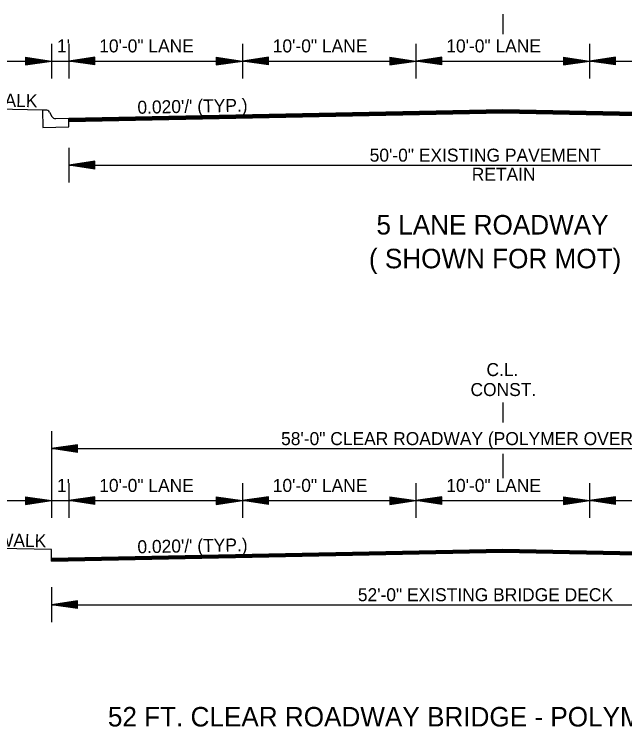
# Model space of a CAD drawing. Extents: x 550980 to 1930787, y -1972975 to 596640.
# Drawn here: x 551281.8 to 551633.5, y -1966644.6 to -1966233.8 of the extents above; entities that cross this region are included whole.
import ezdxf

# ---------------------------------------------------------------- set-up
doc = ezdxf.new("R2010")
doc.units = 0
doc.layers.add('R_Border', color=7, linetype='Continuous')
doc.layers.add('R_Draft', color=7, linetype='Continuous')

msp = doc.modelspace()

# ---------------------------------------------------------------- linework, layer by layer
at = {"layer": 'R_Border'}
for p, q in [((551563.18, -1966233.82), (551563.18, -1966245.39)), ((551303.18, -1966250.82), (551303.18, -1966270.82)), ((551313.18, -1966250.82), (551313.18, -1966270.82)), ((551413.18, -1966250.82), (551413.18, -1966270.82)), ((551513.18, -1966250.82), (551513.18, -1966270.82)), ((551613.18, -1966250.82), (551613.18, -1966270.82)), ((551288.18, -1966258.57), (551303.18, -1966260.82)), ((551288.18, -1966258.57), (551288.18, -1966263.07)), ((551288.18, -1966258.95), (551300.67, -1966260.82)), ((551288.18, -1966259.33), (551298.09, -1966260.82)), ((551288.18, -1966259.71), (551295.6, -1966260.82)), ((551288.18, -1966260.1), (551293.05, -1966260.82)), ((551328.18, -1966258.57), (551313.18, -1966260.82)), ((551328.18, -1966258.95), (551315.68, -1966260.82)), ((551328.18, -1966259.33), (551318.26, -1966260.82)), ((551328.18, -1966259.71), (551320.76, -1966260.82)), ((551328.18, -1966260.09), (551323.3, -1966260.82)), ((551328.18, -1966263.07), (551328.18, -1966258.57)), ((551398.18, -1966258.57), (551413.18, -1966260.82)), ((551398.18, -1966258.57), (551398.18, -1966263.07)), ((551398.18, -1966258.95), (551410.67, -1966260.82)), ((551398.18, -1966259.33), (551408.09, -1966260.82)), ((551398.18, -1966259.71), (551405.6, -1966260.82)), ((551398.18, -1966260.1), (551403.05, -1966260.82)), ((551428.18, -1966258.57), (551413.18, -1966260.82)), ((551428.18, -1966258.95), (551415.68, -1966260.82)), ((551428.18, -1966259.33), (551418.26, -1966260.82)), ((551428.18, -1966259.71), (551420.76, -1966260.82)), ((551428.18, -1966260.09), (551423.3, -1966260.82)), ((551428.18, -1966263.07), (551428.18, -1966258.57)), ((551498.18, -1966258.57), (551513.18, -1966260.82)), ((551498.18, -1966258.57), (551498.18, -1966263.07)), ((551498.18, -1966258.95), (551510.67, -1966260.82)), ((551498.18, -1966259.33), (551508.09, -1966260.82)), ((551498.18, -1966259.71), (551505.6, -1966260.82)), ((551498.18, -1966260.1), (551503.05, -1966260.82)), ((551528.18, -1966258.57), (551513.18, -1966260.82)), ((551528.18, -1966258.95), (551515.68, -1966260.82)), ((551528.18, -1966259.33), (551518.26, -1966260.82)), ((551528.18, -1966259.71), (551520.76, -1966260.82)), ((551528.18, -1966260.09), (551523.3, -1966260.82)), ((551528.18, -1966263.07), (551528.18, -1966258.57)), ((551598.18, -1966258.57), (551613.18, -1966260.82)), ((551598.18, -1966258.57), (551598.18, -1966263.07)), ((551598.18, -1966258.95), (551610.67, -1966260.82)), ((551598.18, -1966259.33), (551608.09, -1966260.82)), ((551598.18, -1966259.71), (551605.6, -1966260.82)), ((551598.18, -1966260.1), (551603.05, -1966260.82)), ((551628.18, -1966258.57), (551613.18, -1966260.82)), ((551628.18, -1966258.95), (551615.68, -1966260.82)), ((551628.18, -1966259.33), (551618.26, -1966260.82)), ((551628.18, -1966259.71), (551620.76, -1966260.82)), ((551628.18, -1966260.09), (551623.3, -1966260.82)), ((551628.18, -1966263.07), (551628.18, -1966258.57)), ((551273.18, -1966260.82), (551853.18, -1966260.82)), ((551288.18, -1966260.47), (551290.55, -1966260.82)), ((551288.18, -1966263.07), (551303.18, -1966260.82)), ((551288.18, -1966261.56), (551293.05, -1966260.82)), ((551288.18, -1966262.32), (551298.09, -1966260.82)), ((551288.18, -1966262.7), (551300.67, -1966260.82)), ((551288.18, -1966261.94), (551295.6, -1966260.82)), ((551288.18, -1966261.18), (551290.55, -1966260.82)), ((551328.18, -1966263.07), (551313.18, -1966260.82)), ((551328.18, -1966262.7), (551315.68, -1966260.82)), ((551328.18, -1966262.32), (551318.26, -1966260.82)), ((551328.18, -1966261.94), (551320.76, -1966260.82)), ((551328.18, -1966261.55), (551323.3, -1966260.82)), ((551328.18, -1966260.47), (551325.81, -1966260.82)), ((551328.18, -1966261.18), (551325.81, -1966260.82)), ((551398.18, -1966260.47), (551400.55, -1966260.82)), ((551398.18, -1966263.07), (551413.18, -1966260.82)), ((551398.18, -1966261.56), (551403.05, -1966260.82)), ((551398.18, -1966262.32), (551408.09, -1966260.82)), ((551398.18, -1966262.7), (551410.67, -1966260.82)), ((551398.18, -1966261.94), (551405.6, -1966260.82)), ((551398.18, -1966261.18), (551400.55, -1966260.82)), ((551428.18, -1966263.07), (551413.18, -1966260.82)), ((551428.18, -1966262.7), (551415.68, -1966260.82)), ((551428.18, -1966262.32), (551418.26, -1966260.82)), ((551428.18, -1966261.94), (551420.76, -1966260.82)), ((551428.18, -1966261.55), (551423.3, -1966260.82)), ((551428.18, -1966260.47), (551425.81, -1966260.82)), ((551428.18, -1966261.18), (551425.81, -1966260.82)), ((551498.18, -1966260.47), (551500.55, -1966260.82)), ((551498.18, -1966263.07), (551513.18, -1966260.82)), ((551498.18, -1966261.56), (551503.05, -1966260.82)), ((551498.18, -1966262.32), (551508.09, -1966260.82)), ((551498.18, -1966262.7), (551510.67, -1966260.82)), ((551498.18, -1966261.94), (551505.6, -1966260.82)), ((551498.18, -1966261.18), (551500.55, -1966260.82)), ((551528.18, -1966263.07), (551513.18, -1966260.82)), ((551528.18, -1966262.7), (551515.68, -1966260.82)), ((551528.18, -1966262.32), (551518.26, -1966260.82)), ((551528.18, -1966261.94), (551520.76, -1966260.82)), ((551528.18, -1966261.55), (551523.3, -1966260.82)), ((551528.18, -1966260.47), (551525.81, -1966260.82)), ((551528.18, -1966261.18), (551525.81, -1966260.82)), ((551598.18, -1966260.47), (551600.55, -1966260.82)), ((551598.18, -1966263.07), (551613.18, -1966260.82)), ((551598.18, -1966261.56), (551603.05, -1966260.82)), ((551598.18, -1966262.32), (551608.09, -1966260.82)), ((551598.18, -1966262.7), (551610.67, -1966260.82)), ((551598.18, -1966261.94), (551605.6, -1966260.82)), ((551598.18, -1966261.18), (551600.55, -1966260.82)), ((551628.18, -1966263.07), (551613.18, -1966260.82)), ((551628.18, -1966262.7), (551615.68, -1966260.82)), ((551628.18, -1966262.32), (551618.26, -1966260.82)), ((551628.18, -1966261.94), (551620.76, -1966260.82)), ((551628.18, -1966261.55), (551623.3, -1966260.82)), ((551628.18, -1966260.47), (551625.81, -1966260.82)), ((551628.18, -1966261.18), (551625.81, -1966260.82)), ((551298.08, -1966289.13), (551238.08, -1966287.93)), ((551313.18, -1966310.82), (551313.18, -1966330.82)), ((551328.18, -1966318.57), (551313.18, -1966320.82)), ((551313.18, -1966320.82), (551813.18, -1966320.82)), ((551328.18, -1966323.07), (551313.18, -1966320.82)), ((551328.18, -1966318.95), (551315.68, -1966320.82)), ((551328.18, -1966322.7), (551315.68, -1966320.82)), ((551328.18, -1966319.33), (551318.26, -1966320.82)), ((551328.18, -1966322.32), (551318.26, -1966320.82)), ((551328.18, -1966319.71), (551320.76, -1966320.82)), ((551328.18, -1966321.94), (551320.76, -1966320.82)), ((551328.18, -1966320.09), (551323.3, -1966320.82)), ((551328.18, -1966321.55), (551323.3, -1966320.82)), ((551328.18, -1966320.47), (551325.81, -1966320.82)), ((551328.18, -1966321.18), (551325.81, -1966320.82)), ((551328.18, -1966323.07), (551328.18, -1966318.57)), ((551563.18, -1966457.67), (551563.18, -1966469.24)), ((551303.18, -1966474.25), (551303.18, -1966524.25)), ((551318.18, -1966482), (551303.18, -1966484.25)), ((551318.18, -1966486.5), (551318.18, -1966482)), ((551303.18, -1966484.25), (551823.18, -1966484.25)), ((551318.18, -1966486.5), (551303.18, -1966484.25)), ((551318.18, -1966482.37), (551305.68, -1966484.25)), ((551318.18, -1966486.12), (551305.68, -1966484.25)), ((551318.18, -1966482.76), (551308.26, -1966484.25)), ((551318.18, -1966485.74), (551308.26, -1966484.25)), ((551318.18, -1966483.13), (551310.76, -1966484.25)), ((551318.18, -1966485.37), (551310.76, -1966484.25)), ((551318.18, -1966483.51), (551313.3, -1966484.25)), ((551318.18, -1966484.98), (551313.3, -1966484.25)), ((551318.18, -1966483.9), (551315.81, -1966484.25)), ((551318.18, -1966484.6), (551315.81, -1966484.25)), ((551563.18, -1966487.25), (551563.18, -1966501.25)), ((551303.18, -1966504.25), (551303.18, -1966524.25)), ((551313.18, -1966504.25), (551313.18, -1966524.25)), ((551413.18, -1966504.25), (551413.18, -1966524.25)), ((551513.18, -1966504.25), (551513.18, -1966524.25)), ((551613.18, -1966504.25), (551613.18, -1966524.25)), ((551273.18, -1966514.25), (551853.18, -1966514.25)), ((551288.18, -1966512), (551303.18, -1966514.25)), ((551288.18, -1966512), (551288.18, -1966516.5)), ((551288.18, -1966512.37), (551300.67, -1966514.25)), ((551288.18, -1966512.76), (551298.09, -1966514.25)), ((551288.18, -1966513.13), (551295.6, -1966514.25)), ((551288.18, -1966513.52), (551293.05, -1966514.25)), ((551288.18, -1966513.9), (551290.55, -1966514.25)), ((551288.18, -1966516.5), (551303.18, -1966514.25)), ((551288.18, -1966514.98), (551293.05, -1966514.25)), ((551288.18, -1966515.74), (551298.09, -1966514.25)), ((551288.18, -1966516.12), (551300.67, -1966514.25)), ((551288.18, -1966515.37), (551295.6, -1966514.25)), ((551288.18, -1966514.6), (551290.55, -1966514.25)), ((551328.18, -1966512), (551313.18, -1966514.25)), ((551328.18, -1966516.5), (551313.18, -1966514.25)), ((551328.18, -1966512.37), (551315.68, -1966514.25)), ((551328.18, -1966516.12), (551315.68, -1966514.25)), ((551328.18, -1966512.76), (551318.26, -1966514.25)), ((551328.18, -1966515.74), (551318.26, -1966514.25)), ((551328.18, -1966513.13), (551320.76, -1966514.25)), ((551328.18, -1966515.37), (551320.76, -1966514.25)), ((551328.18, -1966513.51), (551323.3, -1966514.25)), ((551328.18, -1966514.98), (551323.3, -1966514.25)), ((551328.18, -1966513.9), (551325.81, -1966514.25)), ((551328.18, -1966514.6), (551325.81, -1966514.25)), ((551328.18, -1966516.5), (551328.18, -1966512)), ((551398.18, -1966512), (551413.18, -1966514.25)), ((551398.18, -1966512), (551398.18, -1966516.5)), ((551398.18, -1966512.37), (551410.67, -1966514.25)), ((551398.18, -1966512.76), (551408.09, -1966514.25)), ((551398.18, -1966513.13), (551405.6, -1966514.25)), ((551398.18, -1966513.52), (551403.05, -1966514.25)), ((551398.18, -1966513.9), (551400.55, -1966514.25)), ((551398.18, -1966516.5), (551413.18, -1966514.25)), ((551398.18, -1966514.98), (551403.05, -1966514.25)), ((551398.18, -1966515.74), (551408.09, -1966514.25)), ((551398.18, -1966516.12), (551410.67, -1966514.25)), ((551398.18, -1966515.37), (551405.6, -1966514.25)), ((551398.18, -1966514.6), (551400.55, -1966514.25)), ((551428.18, -1966512), (551413.18, -1966514.25)), ((551428.18, -1966516.5), (551413.18, -1966514.25)), ((551428.18, -1966512.37), (551415.68, -1966514.25)), ((551428.18, -1966516.12), (551415.68, -1966514.25)), ((551428.18, -1966512.76), (551418.26, -1966514.25)), ((551428.18, -1966515.74), (551418.26, -1966514.25)), ((551428.18, -1966513.13), (551420.76, -1966514.25)), ((551428.18, -1966515.37), (551420.76, -1966514.25)), ((551428.18, -1966513.51), (551423.3, -1966514.25)), ((551428.18, -1966514.98), (551423.3, -1966514.25)), ((551428.18, -1966513.9), (551425.81, -1966514.25)), ((551428.18, -1966514.6), (551425.81, -1966514.25)), ((551428.18, -1966516.5), (551428.18, -1966512)), ((551498.18, -1966512), (551513.18, -1966514.25)), ((551498.18, -1966512), (551498.18, -1966516.5)), ((551498.18, -1966512.37), (551510.67, -1966514.25)), ((551498.18, -1966512.76), (551508.09, -1966514.25)), ((551498.18, -1966513.13), (551505.6, -1966514.25)), ((551498.18, -1966513.52), (551503.05, -1966514.25)), ((551498.18, -1966513.9), (551500.55, -1966514.25)), ((551498.18, -1966516.5), (551513.18, -1966514.25)), ((551498.18, -1966514.98), (551503.05, -1966514.25)), ((551498.18, -1966515.74), (551508.09, -1966514.25)), ((551498.18, -1966516.12), (551510.67, -1966514.25)), ((551498.18, -1966515.37), (551505.6, -1966514.25)), ((551498.18, -1966514.6), (551500.55, -1966514.25)), ((551528.18, -1966512), (551513.18, -1966514.25)), ((551528.18, -1966516.5), (551513.18, -1966514.25)), ((551528.18, -1966512.37), (551515.68, -1966514.25)), ((551528.18, -1966516.12), (551515.68, -1966514.25)), ((551528.18, -1966512.76), (551518.26, -1966514.25)), ((551528.18, -1966515.74), (551518.26, -1966514.25)), ((551528.18, -1966513.13), (551520.76, -1966514.25)), ((551528.18, -1966515.37), (551520.76, -1966514.25)), ((551528.18, -1966513.51), (551523.3, -1966514.25)), ((551528.18, -1966514.98), (551523.3, -1966514.25)), ((551528.18, -1966513.9), (551525.81, -1966514.25)), ((551528.18, -1966514.6), (551525.81, -1966514.25)), ((551528.18, -1966516.5), (551528.18, -1966512)), ((551598.18, -1966512), (551613.18, -1966514.25)), ((551598.18, -1966512), (551598.18, -1966516.5)), ((551598.18, -1966512.37), (551610.67, -1966514.25)), ((551598.18, -1966512.76), (551608.09, -1966514.25)), ((551598.18, -1966513.13), (551605.6, -1966514.25)), ((551598.18, -1966513.52), (551603.05, -1966514.25)), ((551598.18, -1966513.9), (551600.55, -1966514.25)), ((551598.18, -1966516.5), (551613.18, -1966514.25)), ((551598.18, -1966514.98), (551603.05, -1966514.25)), ((551598.18, -1966515.74), (551608.09, -1966514.25)), ((551598.18, -1966516.12), (551610.67, -1966514.25)), ((551598.18, -1966515.37), (551605.6, -1966514.25)), ((551598.18, -1966514.6), (551600.55, -1966514.25)), ((551628.18, -1966512), (551613.18, -1966514.25)), ((551628.18, -1966516.5), (551613.18, -1966514.25)), ((551628.18, -1966512.37), (551615.68, -1966514.25)), ((551628.18, -1966516.12), (551615.68, -1966514.25)), ((551628.18, -1966512.76), (551618.26, -1966514.25)), ((551628.18, -1966515.74), (551618.26, -1966514.25)), ((551628.18, -1966513.13), (551620.76, -1966514.25)), ((551628.18, -1966515.37), (551620.76, -1966514.25)), ((551628.18, -1966513.51), (551623.3, -1966514.25)), ((551628.18, -1966514.98), (551623.3, -1966514.25)), ((551628.18, -1966513.9), (551625.81, -1966514.25)), ((551628.18, -1966514.6), (551625.81, -1966514.25)), ((551628.18, -1966516.5), (551628.18, -1966512)), ((551303.18, -1966564.25), (551303.18, -1966584.25)), ((551318.18, -1966572), (551303.18, -1966574.25)), ((551318.18, -1966572.37), (551305.68, -1966574.25)), ((551318.18, -1966576.5), (551318.18, -1966572)), ((551303.18, -1966574.25), (551823.18, -1966574.25)), ((551318.18, -1966576.5), (551303.18, -1966574.25)), ((551318.18, -1966576.12), (551305.68, -1966574.25)), ((551318.18, -1966572.76), (551308.26, -1966574.25)), ((551318.18, -1966575.74), (551308.26, -1966574.25)), ((551318.18, -1966573.13), (551310.76, -1966574.25)), ((551318.18, -1966575.37), (551310.76, -1966574.25)), ((551318.18, -1966573.51), (551313.3, -1966574.25)), ((551318.18, -1966574.98), (551313.3, -1966574.25)), ((551318.18, -1966573.9), (551315.81, -1966574.25)), ((551318.18, -1966574.6), (551315.81, -1966574.25))]:
    msp.add_line(p, q, dxfattribs=at)
for points in [[(551313.18, -1966293.82), (551563.18, -1966288.82), (551813.18, -1966293.82)], [(551313.18, -1966294.12), (551563.18, -1966289.12), (551813.18, -1966294.12)], [(551313.18, -1966294.42), (551563.18, -1966289.42), (551813.18, -1966294.42)], [(551313.18, -1966294.72), (551563.18, -1966289.72), (551813.18, -1966294.72)], [(551313.18, -1966295.02), (551563.18, -1966290.02), (551813.18, -1966295.02)], [(551313.18, -1966295.32), (551563.18, -1966290.32), (551813.18, -1966295.32)], [(551313.18, -1966295.62), (551563.18, -1966290.62), (551813.18, -1966295.62)], [(551303.18, -1966549.25), (551303.18, -1966542.45), (551243.18, -1966541.25), (551243.18, -1966541.25)], [(551303.18, -1966547.45), (551563.18, -1966542.25), (551823.18, -1966547.45)], [(551303.18, -1966547.75), (551563.18, -1966542.55), (551823.18, -1966547.75)], [(551303.18, -1966548.05), (551563.18, -1966542.85), (551823.18, -1966548.05)], [(551303.18, -1966548.35), (551563.18, -1966543.15), (551823.18, -1966548.35)], [(551303.18, -1966548.65), (551563.18, -1966543.45), (551823.18, -1966548.65)], [(551303.18, -1966548.95), (551563.18, -1966543.75), (551823.18, -1966548.95)], [(551303.18, -1966549.25), (551563.18, -1966544.05), (551823.18, -1966549.25)]]:
    msp.add_lwpolyline(points, dxfattribs=at)
at = {"layer": 'R_Draft'}
for p, q in [((551299.82, -1966289.09), (551298.08, -1966289.13)), ((551302.01, -1966290.3), (551303.49, -1966292.76)), ((551305.68, -1966293.97), (551313.18, -1966293.82))]:
    msp.add_line(p, q, dxfattribs=at)
msp.add_lwpolyline([(551298.08, -1966289.13), (551298.28, -1966299.12), (551313.18, -1966298.83), (551313.18, -1966293.82)], dxfattribs=at)
for centre, start, end in [((551299.87, -1966291.59), 30.944, 91.1458), ((551305.63, -1966291.47), 210.944, 271.1458)]:
    msp.add_arc(centre, 2.5, start, end, dxfattribs=at)

# ---------------------------------------------------------------- texts
at = {"layer": 'R_Border'}
for s, height, p in [("1'", 7.5, (551306.35, -1966255.82)), ('10\'-0" LANE', 7.5, (551330.7, -1966255.82)), ('10\'-0" LANE', 7.5, (551430.7, -1966255.82)), ('10\'-0" LANE', 7.5, (551530.7, -1966255.82)), ('50\'-0" EXISTING PAVEMENT', 7.5, (551486.55, -1966318.82)), ('RETAIN', 7.5, (551545.37, -1966329.82)), ('5 LANE ROADWAY', 11.25, (551490.45, -1966360.82)), ('( SHOWN FOR MOT)', 11.25, (551486.11, -1966380.3)), ('C.L.', 7.5, (551553.85, -1966442.46)), ('CONST.', 7.5, (551544.64, -1966453.96)), ('58\'-0" CLEAR ROADWAY (POLYMER OVERLAY)', 7.5, (551435.5, -1966482.25)), ("1'", 7.5, (551306.35, -1966509.25)), ('10\'-0" LANE', 7.5, (551330.7, -1966509.25)), ('10\'-0" LANE', 7.5, (551430.7, -1966509.25)), ('10\'-0" LANE', 7.5, (551530.7, -1966509.25)), ('52\'-0" EXISTING BRIDGE DECK', 7.5, (551479.73, -1966572.25)), ('52 FT. CLEAR ROADWAY BRIDGE - POLYMER OVERLAY', 11.25, (551335.7, -1966644.48))]:
    msp.add_text(s, height=height, dxfattribs=at).set_placement(p)
for s, rotation, p in [('SIDEWALK', 358.8542, (551243.22, -1966286.47)), ("0.020'/' (TYP.)", 1.1458, (551352.79, -1966291.23)), ('SIDEWALK', 358.8542, (551248.32, -1966540.17)), ("0.020'/' (TYP.)", 1.1458, (551352.79, -1966544.66))]:
    msp.add_text(s, height=7.5, rotation=rotation, dxfattribs=at).set_placement(p)

doc.saveas('drawing.dxf')
